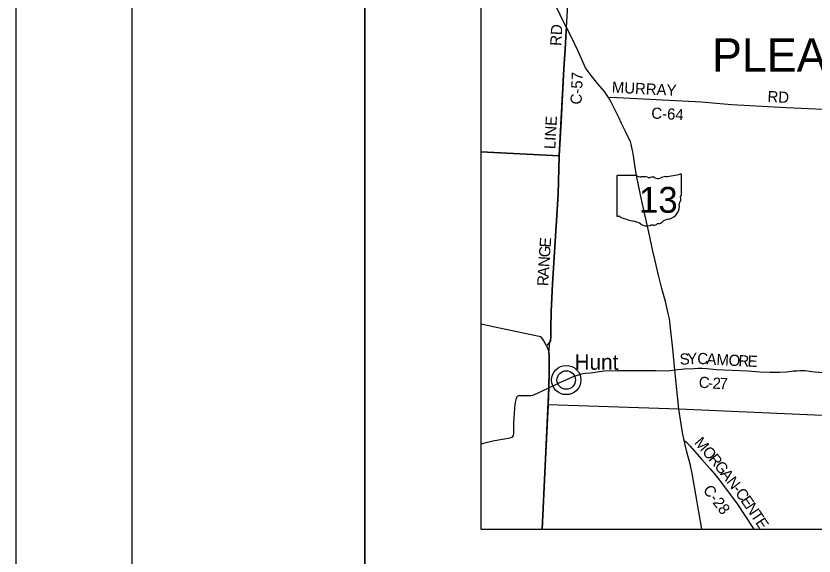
# Model space of a CAD drawing. Extents: x 41.3 to 81.6, y -19.3 to 2.7.
# Drawn here: x 41.265 to 44.697, y -3.71 to -1.388 of the extents above; entities that cross this region are included whole.
import ezdxf

# ---------------------------------------------------------------- set-up
doc = ezdxf.new("R2010")
doc.units = 0
for name, color, linetype in [('GM_X_County_Road', 7, 'Continuous'), ('GM_X_County_Road_Text', 7, 'Continuous'), ('GM_X_State_Route', 7, 'Continuous'), ('GM_X_State_Shield', 7, 'Continuous'), ('GM_X_Township', 7, 'Continuous'), ('GM_X_Township_Road', 7, 'Continuous'), ('GM_X_Township_Text', 7, 'Continuous'), ('GM_X_Unincorporated', 7, 'Continuous'), ('GM_X_Unincorporated_Text', 7, 'Continuous'), ('SH_Border', 7, 'Continuous'), ('SH_Cut_Line', 7, 'Continuous'), ('SH_Data', 7, 'Continuous')]:
    doc.layers.add(name, color=color, linetype=linetype)

msp = doc.modelspace()

# ---------------------------------------------------------------- linework, layer by layer
at = {"layer": 'GM_X_County_Road'}
for points in [[(43.6324, -1.4381), (43.6317, -1.453), (43.6269, -1.5314), (43.6204, -1.6162), (43.6091, -1.8403)], [(43.8136, -1.7386), (43.8235, -1.7369), (44.2133, -1.7575), (44.3416, -1.7695), (44.5781, -1.7814), (44.83, -1.7933), (45.1107, -1.8082), (45.2986, -1.8171), (45.3963, -1.8221), (45.4528, -1.819), (45.534, -1.8224), (45.6163, -1.8262), (45.6407, -1.8258)], [(43.6091, -1.8403), (43.6015, -1.9903), (43.5973, -2.1549), (43.5726, -2.5406), (43.5667, -2.6599), (43.5652, -2.7284), (43.5648, -2.7699), (43.5636, -2.7847), (43.5611, -2.7901), (43.5468, -2.8072), (43.5554, -2.827), (43.5572, -2.8362), (43.5577, -2.8451), (43.5583, -2.9163), (43.5564, -2.987), (43.5531, -3.0596), (43.5412, -3.322), (43.5273, -3.5953)], [(43.5564, -2.987), (43.6016, -2.9657), (43.6343, -2.9511), (43.6661, -2.9371), (43.7041, -2.926), (43.7141, -2.9248), (43.7352, -2.9222), (43.7951, -2.9135), (43.8513, -2.913), (43.9405, -2.9124), (44.0155, -2.9128), (44.0678, -2.9134), (44.0778, -2.9126), (44.0989, -2.9099)], [(44.0989, -2.9099), (44.1383, -2.906), (44.1821, -2.9035), (44.1987, -2.9029), (44.2166, -2.9032), (44.2358, -2.9046), (44.2781, -2.908), (44.413, -2.9146), (44.4642, -2.9177), (44.5085, -2.9197), (44.5482, -2.9202), (44.5794, -2.9185), (44.6089, -2.9148), (44.6228, -2.9136), (44.6359, -2.912), (44.6589, -2.9132), (44.688, -2.9169), (44.9096, -2.9388), (44.9346, -2.9404)], [(43.2645, -3.2292), (43.2756, -3.2257), (43.3156, -3.2155), (43.3896, -3.2025), (43.3976, -3.1999), (43.4017, -3.1967), (43.404, -3.1925), (43.4059, -3.1842), (43.4053, -3.1403), (43.4076, -3.1159), (43.4124, -3.0565), (43.4169, -3.0331), (43.4188, -3.0283), (43.422, -3.0235), (43.4278, -3.0206), (43.4518, -3.02), (43.4787, -3.0197), (43.4883, -3.0181), (43.5082, -3.0098), (43.5564, -2.987)], [(44.1391, -3.2135), (44.1485, -3.2212), (44.1635, -3.237), (44.2141, -3.2947), (44.2485, -3.3336), (44.2757, -3.3663), (44.3637, -3.4822), (44.4387, -3.5953)]]:
    msp.add_lwpolyline(points, dxfattribs=at)
at = {"layer": 'GM_X_State_Route'}
msp.add_lwpolyline([(44.2151, -3.5953), (44.1886, -3.4458), (44.1724, -3.3559), (44.1663, -3.3213), (44.1502, -3.2626), (44.1412, -3.2271), (44.1391, -3.2135), (44.1318, -3.1795), (44.1153, -3.0795), (44.0989, -2.9099), (44.0896, -2.8192), (44.0798, -2.7312), (44.0749, -2.6903), (44.0694, -2.6671), (44.0587, -2.6158), (44.0447, -2.5664), (44.028, -2.5034), (44.0132, -2.4418), (44.0036, -2.3997), (43.9861, -2.318), (43.9569, -2.1851), (43.933, -2.0745), (43.9264, -2.0292), (43.9203, -1.9893), (43.9184, -1.9717), (43.9142, -1.9531), (43.9112, -1.94), (43.9071, -1.9285), (43.9021, -1.9176), (43.8869, -1.8848), (43.8694, -1.8502), (43.8587, -1.8281), (43.8241, -1.7594), (43.8136, -1.7386), (43.7953, -1.7129), (43.7675, -1.6798), (43.7387, -1.6449), (43.7253, -1.6274), (43.7141, -1.6107), (43.6808, -1.5371), (43.6547, -1.4797), (43.6324, -1.4381), (43.6215, -1.4164), (43.5893, -1.35)], dxfattribs=at)
at = {"layer": 'GM_X_State_Shield'}
for p, q in [((43.8488, -2.0775), (43.8488, -2.2465)), ((43.933, -2.0745), (43.8515, -2.0745)), ((44.1272, -2.1588), (44.1272, -2.0704)), ((44.1272, -2.1588), (44.1272, -2.1588))]:
    msp.add_line(p, q, dxfattribs=at)
for centre, major_axis, start_param, end_param in [((43.8519, -2.0771), (0.00323, 0), 1.712693, 3.28349), ((43.9525, -2.0549), (0.0313, 0), 4.042523, 4.731795), ((43.9628, -2.1695), (0.1123, 0), 1.404758, 1.657858), ((43.9883, -2.0762), (0.00903, 0), 3.836095, 5.185415), ((44.0016, -2.0958), (0.0188, 0), 0.950623, 2.079405), ((44.0258, -2.069), (0.0226, 0), 4.081561, 5.145723), ((44.0657, -2.1262), (0.0594, 0), 1.699011, 2.107814), ((44.028, -1.8441), (0.2953, 0), 4.814394, 5.042369), ((44.1241, -2.07), (0.0031, 0), 6.141152, 7.989035), ((44.1265, -2.1653), (0.0048, 0), 1.883978, 3.671073), ((44.1239, -2.1591), (0.00332, 0), 5.05454, 6.418171), ((44.1383, -2.1958), (0.021, 0), 2.387724, 3.262537), ((44.096, -2.1765), (0.0288, 0), 5.934695, 6.695948), ((44.0445, -2.2071), (0.0739, 0), 5.101752, 6.440018), ((43.852, -2.2469), (0.00325, 0), 3.00124, 4.508301), ((43.8525, -2.2296), (0.0248, 0), 4.665946, 4.897461), ((43.8575, -2.2563), (0.00895, 0), 0.519207, 1.627899), ((43.9706, -2.1044), (0.2132, 0), 4.195997, 4.488961), ((44.0757, -2.294), (0.0404, 0), 1.647645, 2.488434), ((43.907, -2.3225), (0.0667, 0), 0.823519, 1.323587), ((43.9792, -2.2571), (0.0423, 0), 4.026481, 4.996735), ((44.0037, -2.3156), (0.0348, 0), 1.495662, 1.94098), ((44.0067, -2.2698), (0.0226, 0), 4.691044, 5.507374), ((44.0271, -2.2861), (0.00635, 0), 1.147584, 2.315152), ((44.0244, -2.2629), (0.0239, 0), 4.937069, 5.64225)]:
    msp.add_ellipse(centre, major_axis=major_axis, ratio=0.8, start_param=start_param, end_param=end_param, dxfattribs=at)
at = {"layer": 'GM_X_Township'}
for points in [[(43.2645, 1.7338), (43.2645, -1.9721), (43.6015, -1.9903), (43.6204, -1.6162), (43.6269, -1.5314), (43.6317, -1.453), (43.6324, -1.4381), (43.6611, -0.9536)], [(44.9265, -3.1148), (44.1153, -3.0795), (43.5531, -3.0596), (43.5564, -2.987), (43.5583, -2.9163), (43.5577, -2.8451), (43.5572, -2.8362), (43.5611, -2.7901), (43.5636, -2.7847), (43.5648, -2.7699), (43.5652, -2.7284), (43.5667, -2.6599), (43.5726, -2.5406), (43.5973, -2.1549), (43.6015, -1.9903), (43.6204, -1.6162), (43.6269, -1.5314), (43.6317, -1.453), (43.6324, -1.4381), (43.6611, -0.9536)], [(44.9265, -3.1148), (44.1153, -3.0795), (43.5531, -3.0596), (43.5412, -3.322), (43.5273, -3.5953), (47.8733, -3.5953)]]:
    msp.add_lwpolyline(points, dxfattribs=at)
msp.add_lwpolyline([(43.2645, -1.9721), (43.2645, -3.5953), (43.5273, -3.5953), (43.5412, -3.322), (43.5564, -2.987), (43.5583, -2.9163), (43.5577, -2.8451), (43.5572, -2.8362), (43.5611, -2.7901), (43.5636, -2.7847), (43.5648, -2.7699), (43.5652, -2.7284), (43.5667, -2.6599), (43.5726, -2.5406), (43.5973, -2.1549), (43.6015, -1.9903)], close=True, dxfattribs=at)
at = {"layer": 'GM_X_Township_Road'}
msp.add_lwpolyline([(43.5468, -2.8072), (43.5345, -2.7852), (43.5261, -2.7724), (43.5212, -2.7686), (43.5154, -2.7659), (43.3171, -2.7254), (43.3058, -2.7227), (43.2645, -2.7129)], dxfattribs=at)
at = {"layer": 'GM_X_Unincorporated'}
for radius in [0.0629, 0.0398]:
    msp.add_circle((43.6314, -2.9536), radius, dxfattribs=at)
at = {"layer": 'SH_Border'}
for points in [[(41.7645, 2.2338), (42.7645, 2.2338), (42.7645, -18.7662), (41.7645, -18.7662)], [(42.7645, 2.2338), (74.7645, 2.2338), (74.7645, -18.7662), (42.7645, -18.7662)]]:
    msp.add_lwpolyline(points, close=True, dxfattribs=at)
at = {"layer": 'SH_Cut_Line'}
msp.add_lwpolyline([(41.2645, -19.2662), (75.2645, -19.2662), (75.2645, 2.7338), (41.2645, 2.7338)], close=True, dxfattribs=at)
at = {"layer": 'SH_Data'}
for p, q in [((43.2645, 1.7338), (43.2645, -3.5953)), ((43.2645, -3.5953), (50.2645, -3.5953))]:
    msp.add_line(p, q, dxfattribs=at)

# ---------------------------------------------------------------- texts
at = {"layer": 'GM_X_County_Road_Text'}
for s, rotation, p in [('RD', 86.5467, (43.6096, -1.518)), ('C-57', 87.2576, (43.6969, -1.7696)), ('MURRAY', 357.0281, (43.8265, -1.7178)), ('RD', 357.0388, (44.496, -1.758)), ('C-64', 356.9156, (43.9963, -1.8291)), ('LINE', 86.9877, (43.5842, -1.9617)), ('E', 86.2389, (43.5641, -2.3848)), ('G', 86.2416, (43.5613, -2.427)), ('N', 86.2416, (43.5586, -2.4691)), ('A', 86.2598, (43.5558, -2.5113)), ('R', 87.1926, (43.5539, -2.5505)), ('S', 4.0514, (44.1212, -2.8887)), ('Y', 2.8169, (44.1533, -2.8864)), ('C', 358.0364, (44.1944, -2.8844)), ('A', 355.6865, (44.2333, -2.8857)), ('M', 356.9481, (44.2765, -2.8889)), ('O', 357.2247, (44.3288, -2.8917)), ('R', 357.2315, (44.371, -2.8938)), ('E', 357.2262, (44.4104, -2.8957)), ('C', 356.1527, (44.2001, -2.9864)), ('2', 357.0828, (44.2599, -2.9904)), ('7', 358.0462, (44.2903, -2.9919)), ('-', 356.4687, (44.2397, -2.9891)), ('M', 310.9784, (44.1791, -3.2246)), ('O', 310.932, (44.2133, -3.2639)), ('R', 309.979, (44.2408, -3.2956)), ('G', 308.4277, (44.2659, -3.3256)), ('A', 307.8622, (44.2921, -3.3586)), ('N', 307.8593, (44.318, -3.3919)), ('C-28', 307.6935, (44.2171, -3.4273)), ('-', 307.8052, (44.344, -3.4252)), ('C', 306.7029, (44.3559, -3.4406)), ('E', 304.7385, (44.3792, -3.4719)), ('N', 303.6123, (44.3995, -3.5012)), ('T', 303.576, (44.4229, -3.5364)), ('E', 303.5724, (44.4427, -3.5663))]:
    msp.add_text(s, height=0.048, rotation=rotation, dxfattribs=at).set_placement(p)
at = {"layer": 'GM_X_State_Shield'}
msp.add_text('13', height=0.11138, dxfattribs=at).set_placement((43.9448, -2.2346))
at = {"layer": 'GM_X_Township_Text'}
msp.add_text('PLEASANT', height=0.144, rotation=0, dxfattribs=at).set_placement((44.2585, -1.628))
at = {"layer": 'GM_X_Unincorporated_Text'}
msp.add_text('Hunt', height=0.06672, rotation=0, dxfattribs=at).set_placement((43.6671, -2.9096))

doc.saveas('drawing.dxf')
